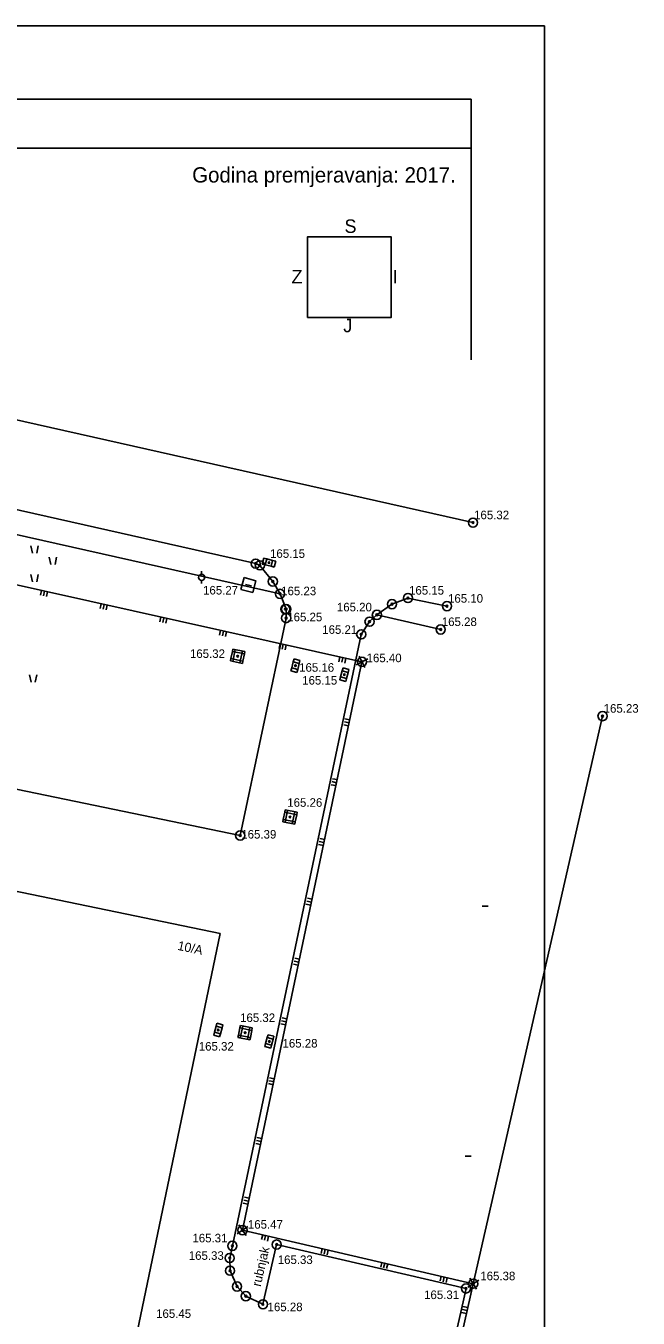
# Model space of a CAD drawing. Extents: x 492698 to 492905, y 5129124 to 5129334.
# Drawn here: x 492855 to 492905.1, y 5129228 to 5129333.7 of the extents above; entities that cross this region are included whole.
import ezdxf

# ---------------------------------------------------------------- set-up
doc = ezdxf.new("R2010")
doc.units = 0
for name, color, linetype in [('KUĆNI BROJ', 7, 'Continuous'), ('MEĐA - stara', 7, 'Continuous'), ('MEĐAŠI', 7, 'Continuous'), ('OBJEKTI - novi', 7, 'Continuous'), ('OBJEKTI - stari', 7, 'Continuous'), ('OBRAZCI', 7, 'Continuous'), ('TOPO - Znakovi', 7, 'Continuous'), ('VISINE', 7, 'Continuous')]:
    doc.layers.add(name, color=color, linetype=linetype)

msp = doc.modelspace()

# ---------------------------------------------------------------- linework, layer by layer
at = {"layer": 'MEĐA - stara'}
for p, q in [((492807.48, 5129311.96), (492891.56, 5129293.06)), ((492873.79, 5129289.71), (492829.27, 5129299.77)), ((492826.05, 5129298.41), (492875.78, 5129287.23)), ((492817.66, 5129296.12), (492882.48, 5129281.67)), ((492855.4, 5129291.17), (492855.53, 5129290.57)), ((492856, 5129291.17), (492855.88, 5129290.57)), ((492856.9, 5129290.24), (492857.03, 5129289.64)), ((492857.5, 5129290.24), (492857.38, 5129289.64)), ((492874.13, 5129289.56), (492873.79, 5129289.71)), ((492875.19, 5129288.24), (492874.13, 5129289.56)), ((492855.4, 5129288.82), (492855.53, 5129288.22)), ((492856, 5129288.82), (492855.88, 5129288.22)), ((492875.78, 5129287.23), (492875.19, 5129288.24)), ((492876.28, 5129285.98), (492875.78, 5129287.23)), ((492884.93, 5129286.39), (492883.7, 5129285.52)), ((492886.24, 5129286.89), (492884.93, 5129286.39)), ((492889.43, 5129286.23), (492886.24, 5129286.89)), ((492872.52, 5129267.46), (492876.28, 5129285.25)), ((492876.28, 5129285.25), (492876.28, 5129285.98)), ((492883.1, 5129284.96), (492883.7, 5129285.52)), ((492883.7, 5129285.52), (492888.92, 5129284.32)), ((492882.42, 5129283.92), (492883.1, 5129284.96)), ((492871.88, 5129233.89), (492882.42, 5129283.92)), ((492872.71, 5129235.17), (492882.48, 5129281.67)), ((492855.28, 5129280.6), (492855.41, 5129280)), ((492855.88, 5129280.6), (492855.76, 5129280)), ((492872.52, 5129267.46), (492820.65, 5129278.19)), ((492902.16, 5129277.23), (492891.58, 5129230.79)), ((492891.58, 5129230.79), (492872.71, 5129235.17)), ((492871.66, 5129232.89), (492871.88, 5129233.89)), ((492875.5, 5129233.99), (492874.38, 5129229.1)), ((492890.99, 5129230.4), (492875.5, 5129233.99)), ((492871.69, 5129231.85), (492871.66, 5129232.89)), ((492872.26, 5129230.56), (492871.69, 5129231.85)), ((492870.12, 5129136.86), (492891.58, 5129230.79)), ((492872.98, 5129229.77), (492872.26, 5129230.56)), ((492881.5, 5129187.83), (492890.99, 5129230.4)), ((492874.38, 5129229.1), (492872.98, 5129229.77))]:
    msp.add_line(p, q, dxfattribs=at)
at = {"layer": 'MEĐAŠI'}
for p, q in [((492882.95, 5129281.91), (492882.01, 5129281.43)), ((492882.24, 5129282.14), (492882.72, 5129281.2)), ((492873.15, 5129235.46), (492872.27, 5129234.88)), ((492872.42, 5129235.61), (492873, 5129234.73)), ((492891.3, 5129231.24), (492891.86, 5129230.34)), ((492892.03, 5129231.07), (492891.13, 5129230.51))]:
    msp.add_line(p, q, dxfattribs=at)
for centre, radius in [((492891.56, 5129293.06), 0.375), ((492891.56, 5129293.06), 0.075), ((492873.79, 5129289.71), 0.375), ((492873.79, 5129289.71), 0.075), ((492873.79, 5129289.71), 0.075), ((492874.13, 5129289.56), 0.375), ((492874.13, 5129289.56), 0.075), ((492875.19, 5129288.24), 0.375), ((492875.19, 5129288.24), 0.075), ((492875.78, 5129287.23), 0.375), ((492875.78, 5129287.23), 0.075), ((492886.24, 5129286.89), 0.375), ((492876.21, 5129285.98), 0.375), ((492876.28, 5129285.98), 0.375), ((492884.93, 5129286.39), 0.375), ((492884.93, 5129286.39), 0.075), ((492886.24, 5129286.89), 0.075), ((492889.43, 5129286.23), 0.375), ((492889.43, 5129286.23), 0.075), ((492876.28, 5129285.25), 0.375), ((492876.21, 5129285.98), 0.075), ((492876.28, 5129285.98), 0.075), ((492876.28, 5129285.25), 0.075), ((492883.1, 5129284.96), 0.375), ((492883.1, 5129284.96), 0.075), ((492883.7, 5129285.52), 0.375), ((492883.7, 5129285.52), 0.075), ((492882.42, 5129283.92), 0.375), ((492882.42, 5129283.92), 0.075), ((492888.92, 5129284.32), 0.375), ((492888.92, 5129284.32), 0.075), ((492882.48, 5129281.67), 0.075), ((492902.16, 5129277.23), 0.375), ((492902.16, 5129277.23), 0.075), ((492872.52, 5129267.46), 0.375), ((492872.52, 5129267.46), 0.075), ((492872.71, 5129235.17), 0.075), ((492875.5, 5129233.99), 0.375), ((492871.66, 5129232.89), 0.375), ((492871.88, 5129233.89), 0.375), ((492871.88, 5129233.89), 0.075), ((492875.5, 5129233.99), 0.075), ((492871.69, 5129231.85), 0.375), ((492871.66, 5129232.89), 0.075), ((492871.69, 5129231.85), 0.075), ((492872.26, 5129230.56), 0.375), ((492872.26, 5129230.56), 0.075), ((492872.98, 5129229.77), 0.375), ((492890.99, 5129230.4), 0.375), ((492890.99, 5129230.4), 0.075), ((492891.58, 5129230.79), 0.075), ((492872.98, 5129229.77), 0.075), ((492874.38, 5129229.1), 0.375), ((492874.38, 5129229.1), 0.075)]:
    msp.add_circle(centre, radius, dxfattribs=at)
for centre, start, end in [((492882.48, 5129281.67), 162.3577, 342.3577), ((492882.48, 5129281.67), 342.3577, 162.3577), ((492872.71, 5129235.17), 168.0246, 348.0246), ((492872.71, 5129235.17), 348.0246, 168.0246), ((492891.58, 5129230.79), 167.1227, 347.1227), ((492891.58, 5129230.79), 347.1227, 167.1227)]:
    msp.add_arc(centre, 0.075, start, end, dxfattribs=at)
at = {"layer": 'OBJEKTI - novi'}
for centre in [(492882.48, 5129281.67), (492872.71, 5129235.17), (492891.58, 5129230.79)]:
    msp.add_circle(centre, 0.375, dxfattribs=at)
at = {"layer": 'OBJEKTI - stari'}
msp.add_lwpolyline([(492818.96, 5129270.18), (492815.01, 5129251.01), (492812.14, 5129237.15), (492810.27, 5129228.29), (492862.15, 5129217.52), (492870.87, 5129259.44)], close=True, dxfattribs=at)
at = {"layer": 'OBRAZCI'}
for p, q in [((492748.91, 5129333.71), (492897.41, 5129333.71)), ((492897.41, 5129333.71), (492897.41, 5129123.71)), ((492754.91, 5129327.71), (492891.41, 5129327.71)), ((492891.41, 5129327.71), (492891.41, 5129306.37)), ((492754.91, 5129323.71), (492891.41, 5129323.71)), ((492892.3, 5129261.68), (492892.8, 5129261.68)), ((492890.91, 5129241.21), (492891.41, 5129241.21))]:
    msp.add_line(p, q, dxfattribs=at)
msp.add_lwpolyline([(492878.01, 5129309.85), (492884.88, 5129309.85), (492884.88, 5129316.44), (492878.01, 5129316.44)], close=True, dxfattribs=at)
msp.add_lwpolyline([(492878.01, 5129309.85), (492884.88, 5129309.85), (492884.88, 5129316.44), (492878.01, 5129316.44)], close=True, dxfattribs=at)
at = {"layer": 'TOPO - Znakovi'}
for p, q in [((492874.45, 5129290.16), (492874.32, 5129289.67)), ((492874.32, 5129289.67), (492874.57, 5129289.61)), ((492874.69, 5129290.09), (492874.45, 5129290.16)), ((492874.69, 5129290.09), (492874.57, 5129289.61)), ((492874.57, 5129289.61), (492875.05, 5129289.49)), ((492875.17, 5129289.97), (492874.69, 5129290.09)), ((492875.17, 5129289.97), (492875.05, 5129289.49)), ((492875.05, 5129289.49), (492875.29, 5129289.42)), ((492875.42, 5129289.91), (492875.17, 5129289.97)), ((492875.29, 5129289.42), (492875.42, 5129289.91)), ((492869.36, 5129288.83), (492869.36, 5129289.08)), ((492869.36, 5129288.33), (492869.36, 5129288.08)), ((492872.83, 5129288.56), (492872.58, 5129287.59)), ((492873.8, 5129288.31), (492872.83, 5129288.56)), ((492873.55, 5129287.34), (492873.8, 5129288.31)), ((492856.19, 5129287.12), (492856.27, 5129287.51)), ((492856.43, 5129287.07), (492856.52, 5129287.46)), ((492856.68, 5129287.01), (492856.76, 5129287.4)), ((492872.58, 5129287.59), (492873.55, 5129287.34)), ((492873.19, 5129287.95), (492872.95, 5129288.01)), ((492873.19, 5129287.95), (492873.43, 5129287.89)), ((492861.07, 5129286.03), (492861.15, 5129286.42)), ((492861.31, 5129285.98), (492861.4, 5129286.37)), ((492861.56, 5129285.92), (492861.64, 5129286.32)), ((492865.95, 5129284.95), (492866.03, 5129285.34)), ((492866.19, 5129284.89), (492866.28, 5129285.28)), ((492866.44, 5129284.84), (492866.52, 5129285.23)), ((492870.83, 5129283.86), (492870.91, 5129284.25)), ((492871.07, 5129283.8), (492871.16, 5129284.19)), ((492871.32, 5129283.75), (492871.4, 5129284.14)), ((492875.71, 5129282.77), (492875.8, 5129283.16)), ((492875.95, 5129282.72), (492876.04, 5129283.11)), ((492876.2, 5129282.66), (492876.28, 5129283.05)), ((492871.76, 5129281.94), (492871.72, 5129281.74)), ((492871.88, 5129282.53), (492871.76, 5129281.94)), ((492872.74, 5129281.73), (492871.76, 5129281.94)), ((492871.92, 5129282.72), (492871.88, 5129282.53)), ((492872.86, 5129282.32), (492871.88, 5129282.53)), ((492872.12, 5129282.68), (492871.91, 5129281.7)), ((492872.9, 5129282.52), (492871.92, 5129282.72)), ((492872.5, 5129281.58), (492872.71, 5129282.56)), ((492872.74, 5129281.73), (492872.86, 5129282.32)), ((492872.86, 5129282.32), (492872.9, 5129282.52)), ((492876.93, 5129281.91), (492876.86, 5129281.67)), ((492877.41, 5129281.78), (492876.93, 5129281.91)), ((492880.59, 5129281.68), (492880.68, 5129282.07)), ((492880.83, 5129281.63), (492880.92, 5129282.02)), ((492881.08, 5129281.57), (492881.16, 5129281.96)), ((492871.72, 5129281.74), (492872.7, 5129281.54)), ((492872.7, 5129281.54), (492872.74, 5129281.73)), ((492876.73, 5129281.18), (492876.67, 5129280.94)), ((492876.67, 5129280.94), (492877.15, 5129280.81)), ((492876.86, 5129281.67), (492876.73, 5129281.18)), ((492877.22, 5129281.05), (492876.73, 5129281.18)), ((492877.35, 5129281.54), (492876.86, 5129281.67)), ((492877.15, 5129280.81), (492877.22, 5129281.05)), ((492877.22, 5129281.05), (492877.35, 5129281.54)), ((492877.35, 5129281.54), (492877.41, 5129281.78)), ((492880.86, 5129280.93), (492880.73, 5129280.44)), ((492880.93, 5129281.17), (492880.86, 5129280.93)), ((492881.35, 5129280.8), (492880.86, 5129280.93)), ((492881.41, 5129281.04), (492880.93, 5129281.17)), ((492881.22, 5129280.31), (492881.35, 5129280.8)), ((492881.35, 5129280.8), (492881.41, 5129281.04)), ((492880.73, 5129280.44), (492880.67, 5129280.2)), ((492880.67, 5129280.2), (492881.15, 5129280.07)), ((492881.22, 5129280.31), (492880.73, 5129280.44)), ((492881.15, 5129280.07), (492881.22, 5129280.31)), ((492881.04, 5129276.76), (492881.43, 5129276.68)), ((492881.09, 5129277), (492881.48, 5129276.92)), ((492880.99, 5129276.51), (492881.38, 5129276.43)), ((492879.96, 5129271.62), (492880.35, 5129271.54)), ((492880.01, 5129271.87), (492880.4, 5129271.78)), ((492880.06, 5129272.11), (492880.45, 5129272.03)), ((492876.16, 5129269.37), (492876.04, 5129268.78)), ((492876.2, 5129269.56), (492876.16, 5129269.37)), ((492877.14, 5129269.16), (492876.16, 5129269.37)), ((492876.4, 5129269.52), (492876.19, 5129268.54)), ((492877.18, 5129269.36), (492876.2, 5129269.56)), ((492876.78, 5129268.42), (492876.99, 5129269.4)), ((492877.02, 5129268.57), (492877.14, 5129269.16)), ((492877.14, 5129269.16), (492877.18, 5129269.36)), ((492876.04, 5129268.78), (492876, 5129268.58)), ((492876, 5129268.58), (492876.98, 5129268.38)), ((492877.02, 5129268.57), (492876.04, 5129268.78)), ((492876.98, 5129268.38), (492877.02, 5129268.57)), ((492879.03, 5129267.22), (492879.43, 5129267.14)), ((492878.93, 5129266.73), (492879.32, 5129266.65)), ((492878.98, 5129266.97), (492879.37, 5129266.89)), ((492877.9, 5129261.84), (492878.3, 5129261.75)), ((492877.96, 5129262.08), (492878.35, 5129262)), ((492878.01, 5129262.32), (492878.4, 5129262.24)), ((492876.88, 5129256.94), (492877.27, 5129256.86)), ((492876.93, 5129257.19), (492877.32, 5129257.1)), ((492876.98, 5129257.43), (492877.37, 5129257.35)), ((492875.9, 5129252.29), (492876.29, 5129252.21)), ((492875.95, 5129252.54), (492876.34, 5129252.46)), ((492870.41, 5129251.37), (492870.35, 5129251.13)), ((492870.54, 5129251.86), (492870.41, 5129251.37)), ((492870.9, 5129251.24), (492870.41, 5129251.37)), ((492870.61, 5129252.1), (492870.54, 5129251.86)), ((492871.03, 5129251.73), (492870.54, 5129251.86)), ((492871.09, 5129251.97), (492870.61, 5129252.1)), ((492870.83, 5129251), (492870.9, 5129251.24)), ((492870.9, 5129251.24), (492871.03, 5129251.73)), ((492871.03, 5129251.73), (492871.09, 5129251.97)), ((492872.49, 5129251.72), (492872.37, 5129251.13)), ((492872.53, 5129251.91), (492872.49, 5129251.72)), ((492873.47, 5129251.51), (492872.49, 5129251.72)), ((492872.73, 5129251.87), (492872.52, 5129250.89)), ((492873.51, 5129251.71), (492872.53, 5129251.91)), ((492873.11, 5129250.77), (492873.32, 5129251.75)), ((492873.35, 5129250.92), (492873.47, 5129251.51)), ((492873.47, 5129251.51), (492873.51, 5129251.71)), ((492875.85, 5129252.05), (492876.24, 5129251.97)), ((492870.35, 5129251.13), (492870.83, 5129251)), ((492872.37, 5129251.13), (492872.33, 5129250.93)), ((492872.33, 5129250.93), (492873.31, 5129250.73)), ((492873.35, 5129250.92), (492872.37, 5129251.13)), ((492873.31, 5129250.73), (492873.35, 5129250.92)), ((492874.6, 5129250.43), (492874.54, 5129250.19)), ((492874.54, 5129250.19), (492875.02, 5129250.06)), ((492874.73, 5129250.92), (492874.6, 5129250.43)), ((492875.09, 5129250.3), (492874.6, 5129250.43)), ((492874.8, 5129251.16), (492874.73, 5129250.92)), ((492875.22, 5129250.79), (492874.73, 5129250.92)), ((492875.28, 5129251.03), (492874.8, 5129251.16)), ((492875.02, 5129250.06), (492875.09, 5129250.3)), ((492875.09, 5129250.3), (492875.22, 5129250.79)), ((492875.22, 5129250.79), (492875.28, 5129251.03)), ((492874.82, 5129247.16), (492875.21, 5129247.07)), ((492874.87, 5129247.4), (492875.26, 5129247.32)), ((492874.92, 5129247.64), (492875.31, 5129247.56)), ((492873.89, 5129242.75), (492874.29, 5129242.67)), ((492873.79, 5129242.26), (492874.18, 5129242.18)), ((492873.84, 5129242.51), (492874.23, 5129242.42)), ((492872.81, 5129237.61), (492873.21, 5129237.53)), ((492872.87, 5129237.86), (492873.26, 5129237.78)), ((492872.76, 5129237.37), (492873.15, 5129237.29)), ((492874.27, 5129234.4), (492874.36, 5129234.79)), ((492874.51, 5129234.34), (492874.6, 5129234.73)), ((492874.75, 5129234.28), (492874.84, 5129234.67)), ((492879.14, 5129233.27), (492879.23, 5129233.66)), ((492879.38, 5129233.21), (492879.47, 5129233.6)), ((492879.62, 5129233.15), (492879.71, 5129233.54)), ((492884.01, 5129232.14), (492884.1, 5129232.53)), ((492884.25, 5129232.08), (492884.34, 5129232.47)), ((492884.49, 5129232.02), (492884.59, 5129232.41)), ((492888.88, 5129231.01), (492888.97, 5129231.4)), ((492889.12, 5129230.95), (492889.21, 5129231.34)), ((492889.37, 5129230.89), (492889.46, 5129231.28)), ((492890.63, 5129228.43), (492891.02, 5129228.34)), ((492890.69, 5129228.67), (492891.08, 5129228.59)), ((492890.74, 5129228.92), (492891.13, 5129228.83))]:
    msp.add_line(p, q, dxfattribs=at)
for centre, radius in [((492874.87, 5129289.79), 0.065), ((492869.36, 5129288.58), 0.25), ((492872.31, 5129282.13), 0.065), ((492877.04, 5129281.36), 0.065), ((492881.04, 5129280.62), 0.065), ((492876.59, 5129268.97), 0.065), ((492870.72, 5129251.55), 0.065), ((492872.92, 5129251.32), 0.065), ((492874.91, 5129250.61), 0.065)]:
    msp.add_circle(centre, radius, dxfattribs=at)

# ---------------------------------------------------------------- texts
at = {"layer": 'KUĆNI BROJ'}
for s, rotation, p in [('10/A', 348.3106, (492867.35, 5129258.11)), ('rubnjak', 77.0995, (492874.19, 5129230.51))]:
    msp.add_text(s, height=0.75, rotation=rotation, dxfattribs=at).set_placement(p)
at = {"layer": 'OBRAZCI'}
for s, height, p in [('Godina premjeravanja: 2017.', 1.25, (492868.59, 5129320.89)), ('S', 1.1, (492881.05, 5129316.77)), ('S', 1.1, (492881.05, 5129316.77)), ('Z', 1.1, (492876.72, 5129312.64)), ('Z', 1.1, (492876.72, 5129312.64)), ('I', 1.1, (492884.98, 5129312.63)), ('I', 1.1, (492884.98, 5129312.63)), ('J', 1.1, (492880.95, 5129308.64)), ('J', 1.1, (492880.95, 5129308.64))]:
    msp.add_text(s, height=height, dxfattribs=at).set_placement(p)
at = {"layer": 'VISINE'}
for s, p in [('165.32', (492891.65, 5129293.34)), ('165.15', (492874.96, 5129290.18)), ('165.27', (492869.48, 5129287.18)), ('165.23', (492875.87, 5129287.12)), ('165.15', (492886.33, 5129287.17)), ('165.10', (492889.52, 5129286.51)), ('165.20', (492880.43, 5129285.8)), ('165.25', (492876.37, 5129284.99)), ('165.28', (492889.01, 5129284.6)), ('165.21', (492879.23, 5129283.96)), ('165.32', (492868.41, 5129281.99)), ('165.40', (492882.86, 5129281.64)), ('165.16', (492877.34, 5129280.86)), ('165.15', (492877.59, 5129279.81)), ('165.23', (492902.25, 5129277.51)), ('165.26', (492876.37, 5129269.81)), ('165.39', (492872.61, 5129267.21)), ('165.32', (492872.51, 5129252.2)), ('165.32', (492869.13, 5129249.86)), ('165.28', (492875.98, 5129250.11)), ('165.47', (492873.15, 5129235.29)), ('165.31', (492868.61, 5129234.17)), ('165.33', (492868.31, 5129232.74)), ('165.33', (492875.59, 5129232.4)), ('165.38', (492892.16, 5129231.07)), ('165.31', (492887.56, 5129229.53)), ('165.28', (492874.76, 5129228.54)), ('165.45', (492865.64, 5129227.99))]:
    msp.add_text(s, height=0.7, dxfattribs=at).set_placement(p)

doc.saveas('drawing.dxf')
